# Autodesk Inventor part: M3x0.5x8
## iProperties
IsCustomPart: 1
Company: 한국ATC센터
Created: 2009-02
Part Number: M3x0.5x8
Material: 강, 연강
Description: 6각 소켓 머리 없는 멈춤 나사
Document SubType Name: Modeling
Standard: KS B 1028
Designer: KYOUNG IL JANG
Standards Organization: KS
Language: ko-KR
Size Designation: 납작점M3x6
Categories: <MemberInstance><Categories><Category DisplayName="조임쇠" InternalName="e4da775c-781d-43d5-af7c-5136215cf5a6" Mnemonic="FSTN"><Category DisplayName="볼트" InternalN
Density: 7.86 g/cm^3
Mass: 0.293227 g
Surface Area: 0.779768 cm^2
Volume: 0.0373062 cm^3
Vendor: CBT Solutions
Author: KYOUNG IL JANG
